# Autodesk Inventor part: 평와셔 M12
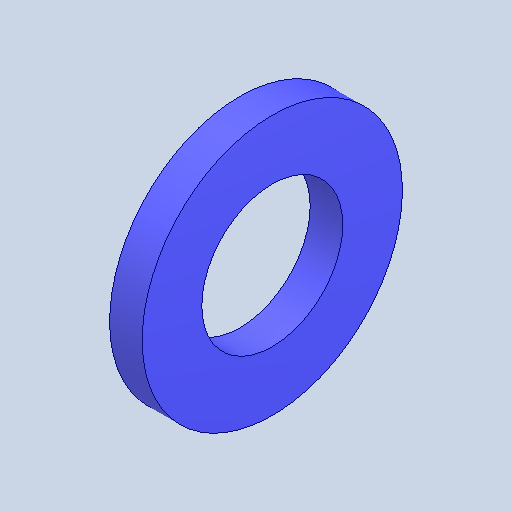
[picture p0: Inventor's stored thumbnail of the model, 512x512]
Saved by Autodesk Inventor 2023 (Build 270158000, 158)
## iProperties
Created: 2025-03
Part Number: 평와셔 M12
Material: 스테인리스강
Description: 평면 와셔
Document SubType Name: Modeling
Designer: User
Density: 8.08 g/cm^3
Appearance: 기본값
Author: jhkim
Sending System: Autodesk Inventor 2025
Preprocessor: ST-DEVELOPER v20
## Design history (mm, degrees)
feature "Solid1"
node "솔리드1"
